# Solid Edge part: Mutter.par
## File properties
Author: Türk
Template: Iso Part.par
Last saved by: Türk
Revision: 8
Application: Solid Edge
Accuracy: 0,990
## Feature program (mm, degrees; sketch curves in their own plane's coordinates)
sketch for "unnamed Hole 1" plane through (0, 0, 0) normal (0, -1, 0) x-axis (1, 0, 0)
  hole centre (0, 0) bore radius 9.7295
hole "unnamed Hole 1" through
pattern "unnamed Pattern 1" of "unnamed Hole 1"
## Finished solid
Body 1: solid body, 21 faces, 44 edges, 24 vertices.
  Faces by surface: cylinder 13, plane 8
  Edges by curve: line 30, ellipse 12, circle 2
Bounding box of the edges (mm): 27.713 x 9.000 x 24.000, from (-13.8564, 0, -12) to (13.8564, 9, 12).
Cylindrical faces by radius (mm): R0.5 x12, R9.7295 x1
Planar faces by outward normal: +y 1, +z 1, -y 1, -z 1, oblique 4
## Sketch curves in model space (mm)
circle centre (0, 0, 0) radius 13.8564
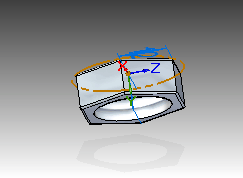
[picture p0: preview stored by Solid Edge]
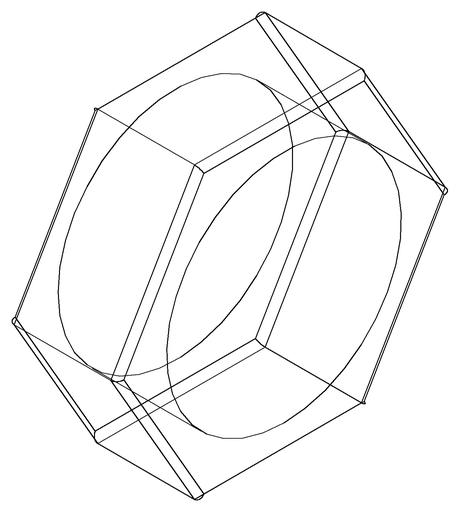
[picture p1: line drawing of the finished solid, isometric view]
